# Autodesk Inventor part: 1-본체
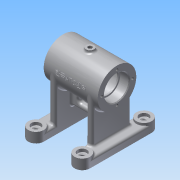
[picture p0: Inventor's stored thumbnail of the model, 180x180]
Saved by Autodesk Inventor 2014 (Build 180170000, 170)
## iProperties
Created: 2015-11
Part Number: 1-본체
Material: 알루미늄 6061
Document SubType Name: Modeling
Designer: 702
Density: 2.71 g/cm^3
Appearance: 알루미늄 - 평지
Mass: 358.848 g
Surface Area: 454.549 cm^2
Volume: 132.416 cm^3
Author: 702
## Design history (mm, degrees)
sketch "스케치1"
  geometry: L1 (-40, -30)-(40, -30); L2 (40, -30)-(40, 30); L3 (40, 30)-(-40, 30); L4 (-40, 30)-(-40, -30); L5 (-40, -30)-(40, 30); L6 (40, -30)-(-40, 30); L7 (-40, 20)-(40, 20); L8 (-40, 40)-(40, 40); L9 (-40, -20)-(40, -20); L10 (-40, -40)-(40, -40); L11 (-4, 20)-(4, 20); L12 (4, 20)-(4, -20); L13 (4, -20)-(-4, -20); L14 (-4, -20)-(-4, 20); L15 (-4, 20)-(4, -20); L16 (4, 20)-(-4, -20); A1 r 10 centre (-40, 30) between (-40, 20) and (-40, 40); A2 r 10 centre (40, 30) between (40, 20) and (40, 40); A3 r 10 centre (-40, -30) between (-40, -20) and (-40, -40); A4 r 10 centre (40, -30) between (40, -20) and (40, -40); 1 further point
  constraints: 32 end point, 8 point on circle, 5 parallel, 4 centre point, 4 coincident, 4 midpoint, 3 equal radius, 3 perpendicular, 3 point on line, 3 tangent, 2 horizontal, 1 collinear
  dimensions: "d0" = 80 distance of L2.end L3.end; "d1" = 60 distance of L1.end L2.end; "d2" = 20 diameter of A1; "d3" = 8 distance of L11.start L11.end
extrude "돌출1" new body sketch "스케치1" distance "d4" = 10; taper "d5" = 0 deg
extrude "돌출2" join sketch "스케치1" distance "d6" = 13; taper "d7" = 0 deg
sketch "스케치2"
  geometry: L1 (0, 0)-(0, 68); C1 r 25 at (0, 68)
  constraints: 2 end point, 1 centre point, 1 coincident, 1 vertical
  dimensions: "d8" = 68 distance of L1.start L1.end; "d9" = 50 diameter of C1
extrude "돌출3" join sketch "스케치2" stored distance "d10" = 70; taper "d11" = 0 deg
sketch "스케치3"
  geometry: L1 (40, -20)-(-40, -20) reference; L2 (-25, -28)-(25, -28); L3 (25, -28)-(25, -20); L4 (25, -20)-(-25, -20); L5 (-25, -20)-(-25, -28); L6 (40, -20)-(-40, -20) reference; L7 (0, 0)-(46.4, 0); L8 (-25, 28)-(25, 28); L9 (25, 28)-(25, 20); L10 (25, 20)-(-25, 20); L11 (-25, 20)-(-25, 28); 2 further points
  constraints: 18 end point, 5 symmetric about line, 3 parallel, 2 midpoint, 1 horizontal, 1 perpendicular
  dimensions: "d12" = 8 distance of L2.end L3.end; "d13" = 50 distance of L2.start L2.end
extrude "돌출4" join sketch "스케치3" stored distance "d14" = 70; taper "d15" = 0 deg
sketch "스케치4"
  geometry: L1 (-35, 48)-(35, 48); L2 (-22.5, 23)-(22.5, 23); L3 (22.5, 23)-(22.5, 48); L4 (22.5, 48)-(-22.5, 48); L5 (-22.5, 48)-(-22.5, 23); L6 (-20, 0)-(-40, 0) reference; 2 further points
  constraints: 10 end point, 2 midpoint, 1 horizontal, 1 parallel, 1 perpendicular
  dimensions: "d18" = 45 distance of L2.start L2.end; "d64" = 23 distance between parallel lines of L6 L2; "d65" = 25 distance of L4.end L2.start
extrude "돌출5" join sketch "스케치4" stored distance "d19" = 8; taper "d20" = 0 deg
sketch "스케치5"
  geometry: L1 (-23, -20)-(-23, 20) reference; L2 (0, 0)-(-33, 0); L3 (-33, 11.5)-(-33, -8); L4 (-36.5, -8)-(-36.5, 8); L5 (-29.5, -8)-(-29.5, 8); A1 r 3.5 centre (-33, 8) between (-36.5, 8) and (-29.5, 8); A2 r 3.5 centre (-33, -8) between (-36.5, -8) and (-29.5, -8)
  constraints: 8 end point, 5 point on circle, 3 tangent, 2 centre point, 2 perpendicular, 2 point on line, 1 coincident, 1 equal radius, 1 parallel, 1 vertical alignment
  dimensions: "d21" = 33 distance of L2.end L2.start; "d22" = 7 diameter of A1; "d23" = 23 dimension on A1 A2
extrude "돌출6" cut sketch "스케치5" stored distance "d24" = 8; taper "d25" = 0 deg
sketch "스케치6"
  geometry: C1 r 10 at (0, 0) reference; 1 further point
hole "구멍1" sketch "스케치6" at (0, 0) diameter "d26" = 6; stored, may be unused: countersink angle "d30" = 90 deg, drill point angle "d32" = 118 deg; dims "d27" = 6, "d28" = 12, "d29" = 4, "d31" = 8
fillet "모깎기1" dims "d33" = 0.3
chamfer "모따기1" distance "d34" = 1; stored, may be unused: second distance "d35" = 2, angle "d36" = 45 deg
sketch "스케치7"
  geometry: C1 r 25 at (0, 0) reference; 1 further point
hole "구멍2" sketch "스케치7" at (0, 0) diameter "d37" = 28; stored, may be unused: countersink angle "d41" = 90 deg, drill point angle "d43" = 118 deg; dims "d38" = 6, "d39" = 32, "d40" = 12, "d42" = 8
sketch "스케치8"
  geometry: C1 r 14 at (0, 68) reference; C2 r 21 at (0, 68); 1 further point
  constraints: 1 centre point, 1 coincident
  dimensions: "d44" = 42 diameter of C2
extrude "돌출7" cut sketch "스케치8" stored distance "d45" = 42; taper "d46" = 0 deg
sketch "스케치9"
  geometry: L1 (-21, 89)-(21, 89) reference; L2 (-35, 93)-(35, 93) reference; L3 (35, 43)-(35, 93) reference; L4 (-35, 93)-(-35, 43) reference; L5 (0, 89)-(5, 89); L6 (5, 89)-(5, 96); L7 (5, 96)-(0, 96); L8 (0, 96)-(0, 89); 1 further point
  constraints: 8 end point, 2 parallel, 1 collinear, 1 horizontal, 1 perpendicular
  dimensions: "d48" = 5 distance of L6.end L7.end; "d49" = 35 distance between parallel lines of L3 L8; "d50" = 3 distance between parallel lines of L2 L7
revolve "회전1" sketch "스케치9" stored, may be unused: angle "d51" = 90 deg
sketch "스케치10" dims "d52" = 40
  geometry: C1 r 25 at (0, 0) reference; 3 further points
  constraints: 1 coincident, 1 vertical alignment, 2 other
hole "구멍3" sketch "스케치10" at (0, -20) diameter "d53" = 3.242; stored, may be unused: countersink angle "d57" = 90 deg, drill point angle "d59" = 118 deg; dims "d54" = 8, "d55" = 4, "d56" = 2, "d58" = 10
fillet "모깎기2" dims "d66" = 3
fillet "모깎기3" dims "d67" = 3
fillet "모깎기4" dims "d68" = 3
chamfer "모따기2" distance "d69" = 1; stored, may be unused: second distance "d70" = 2, angle "d71" = 45 deg
fillet "모깎기5" dims "d72" = 0.3, "d73" = 3
sketch "스케치11"
  geometry: A1 r 5 centre (0, 0) between (0, -5) and (0, 5) reference; A2 r 5 centre (0, 0) between (0, 5) and (0, -5) reference
hole "구멍4" sketch "스케치11" at (0, 0) diameter "d74" = 4.917; stored, may be unused: countersink angle "d78" = 90 deg, drill point angle "d80" = 118 deg; dims "d75" = 8, "d76" = 4, "d77" = 2, "d79" = 10
sketch "스케치12"
  geometry: L1 (0, 68)-(0, 22.904); L2 (41.832, 68)-(76.847, 68); L3 (76.847, 68)-(76.847, 60.104); L4 (76.847, 60.104)-(41.832, 60.104); L5 (41.832, 60.104)-(41.832, 68); L6 (14, 43.751)-(8.804, 40.751); L7 (11.305, 48.42)-(14, 43.751); L8 (5.703, 46.122)-(8.804, 40.751); C1 r 14 at (0, 68) reference; A1 r 22.609 centre (0, 68) between (5.703, 46.122) and (11.305, 48.42); 1 further point
  constraints: 16 end point, 2 parallel, 2 perpendicular, 2 point on circle, 1 centre point, 1 coincident, 1 horizontal, 1 vertical
  dimensions: "d82" = 28 distance of L1.start L6.start; "d84" = 6 distance between parallel lines of L7 L8
revolve "회전2" sketch "스케치12" stored, may be unused: angle "d85" = 90 deg
fillet "모깎기6" dims "d86" = 3
sketch "스케치13"
  geometry: A1 r 6 centre (0, 0) between (0, 6) and (0, -6) reference; 1 further point
hole "구멍5" sketch "스케치13" at (0, 0) diameter "d87" = 4.917; stored, may be unused: countersink angle "d91" = 90 deg, drill point angle "d93" = 118 deg; dims "d88" = 8, "d89" = 4, "d90" = 2, "d92" = 10
node "작업 평면1"
sketch "스케치14"
  geometry: L1 (-5, 96)-(5, 96) reference; 3 further points
  constraints: 1 midpoint, 1 vertical alignment, 1 other
  dimensions: "d95" = 25 distance of point (0, 96) point (0, 71)
feature "엠보싱1" sketch "스케치14" dims "d4" = 10, "d5" = 0, "d96" = 0.5, "d97" = 0
fillet "모깎기7" dims "d98" = 3
node "솔리드1"
mirror "대칭1"
mirror "대칭2"
mirror "대칭3"
pattern_circular "원형 패턴1" dims angle "d61" = 360 deg
mirror "대칭4"
other parameters: "d81" = 30 deg, "d83" = 6, "d94" = 25
